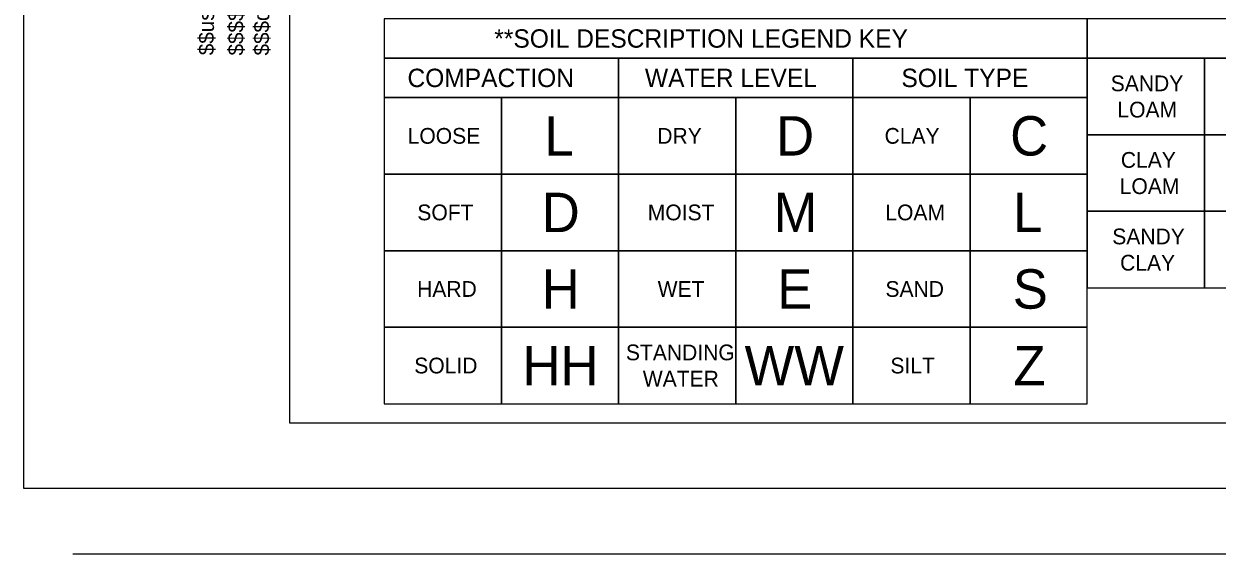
# Model space of a CAD drawing. Extents: x 14330 to 16126, y 15844 to 16994.
# Drawn here: x 14329.7 to 14784.3, y 15843.6 to 16045.6 of the extents above; entities that cross this region are included whole.
import ezdxf

# ---------------------------------------------------------------- set-up
doc = ezdxf.new("R2010")
doc.units = 0
for name, color, linetype in [('RD_SHT_Bndy', 7, 'Continuous'), ('RD_SHT_ID', 7, 'Continuous'), ('RD_SHT_Iplotshp', 7, 'Continuous'), ('RD_SHT_Snap', 7, 'Continuous'), ('RD_SHT_TX', 7, 'Continuous')]:
    doc.layers.add(name, color=color, linetype=linetype)

msp = doc.modelspace()

# ---------------------------------------------------------------- linework, layer by layer
at = {"layer": 'RD_SHT_Bndy'}
for p, q in [((14430.85, 16943.63), (14430.85, 15893.63)), ((14430.85, 16043.63), (14430.85, 15893.68)), ((14430.85, 15893.63), (16105.85, 15893.63)), ((16108.25, 15868.63), (14348.25, 15868.63)), ((16108.25, 15843.63), (14348.25, 15843.63))]:
    msp.add_line(p, q, dxfattribs=at)
for points in [[(14466.94, 16032.5), (14734.84, 16032.5), (14734.84, 16047.5), (14466.94, 16047.5)], [(14734.84, 16032.5), (15002.74, 16032.5), (15002.74, 16047.5), (14734.84, 16047.5)], [(14466.94, 16017.5), (14556.24, 16017.5), (14556.24, 16032.5), (14466.94, 16032.5)], [(14556.24, 16017.5), (14645.54, 16017.5), (14645.54, 16032.5), (14556.24, 16032.5)], [(14645.54, 16017.5), (14734.84, 16017.5), (14734.84, 16032.5), (14645.54, 16032.5)], [(14734.84, 16003.34), (14779.49, 16003.34), (14779.49, 16032.5), (14734.84, 16032.5)], [(14779.49, 16003.34), (14824.14, 16003.34), (14824.14, 16032.5), (14779.49, 16032.5)], [(14466.94, 15988.34), (14511.59, 15988.34), (14511.59, 16017.5), (14466.94, 16017.5)], [(14511.59, 15988.34), (14556.24, 15988.34), (14556.24, 16017.5), (14511.59, 16017.5)], [(14556.24, 15988.34), (14600.89, 15988.34), (14600.89, 16017.5), (14556.24, 16017.5)], [(14600.89, 15988.34), (14645.54, 15988.34), (14645.54, 16017.5), (14600.89, 16017.5)], [(14645.54, 15988.34), (14690.19, 15988.34), (14690.19, 16017.5), (14645.54, 16017.5)], [(14690.19, 15988.34), (14734.84, 15988.34), (14734.84, 16017.5), (14690.19, 16017.5)], [(14734.84, 15974.18), (14779.49, 15974.18), (14779.49, 16003.34), (14734.84, 16003.34)], [(14779.49, 15974.18), (14824.14, 15974.18), (14824.14, 16003.34), (14779.49, 16003.34)], [(14466.94, 15959.18), (14511.59, 15959.18), (14511.59, 15988.34), (14466.94, 15988.34)], [(14511.59, 15959.18), (14556.24, 15959.18), (14556.24, 15988.34), (14511.59, 15988.34)], [(14556.24, 15959.18), (14600.89, 15959.18), (14600.89, 15988.34), (14556.24, 15988.34)], [(14600.89, 15959.18), (14645.54, 15959.18), (14645.54, 15988.34), (14600.89, 15988.34)], [(14645.54, 15959.18), (14690.19, 15959.18), (14690.19, 15988.34), (14645.54, 15988.34)], [(14690.19, 15959.18), (14734.84, 15959.18), (14734.84, 15988.34), (14690.19, 15988.34)], [(14734.84, 15945.03), (14779.49, 15945.03), (14779.49, 15974.18), (14734.84, 15974.18)], [(14779.49, 15945.03), (14824.14, 15945.03), (14824.14, 15974.18), (14779.49, 15974.18)], [(14466.94, 15930.03), (14511.59, 15930.03), (14511.59, 15959.18), (14466.94, 15959.18)], [(14511.59, 15930.03), (14556.24, 15930.03), (14556.24, 15959.18), (14511.59, 15959.18)], [(14556.24, 15930.03), (14600.89, 15930.03), (14600.89, 15959.18), (14556.24, 15959.18)], [(14600.89, 15930.03), (14645.54, 15930.03), (14645.54, 15959.18), (14600.89, 15959.18)], [(14645.54, 15930.03), (14690.19, 15930.03), (14690.19, 15959.18), (14645.54, 15959.18)], [(14690.19, 15930.03), (14734.84, 15930.03), (14734.84, 15959.18), (14690.19, 15959.18)], [(14466.94, 15900.87), (14511.59, 15900.87), (14511.59, 15930.03), (14466.94, 15930.03)], [(14511.59, 15900.87), (14556.24, 15900.87), (14556.24, 15930.03), (14511.59, 15930.03)], [(14556.24, 15900.87), (14600.89, 15900.87), (14600.89, 15930.03), (14556.24, 15930.03)], [(14600.89, 15900.87), (14645.54, 15900.87), (14645.54, 15930.03), (14600.89, 15930.03)], [(14645.54, 15900.87), (14690.19, 15900.87), (14690.19, 15930.03), (14645.54, 15930.03)], [(14690.19, 15900.87), (14734.84, 15900.87), (14734.84, 15930.03), (14690.19, 15930.03)]]:
    msp.add_lwpolyline(points, close=True, dxfattribs=at)
at = {"layer": 'RD_SHT_Iplotshp'}
msp.add_lwpolyline([(14329.65, 16968.63), (16125.65, 16968.63), (16125.65, 15868.63), (14329.65, 15868.63)], close=True, dxfattribs=at)
at = {"layer": 'RD_SHT_Snap'}
msp.add_line((14329.65, 15868.63), (14329.65, 16968.63), dxfattribs=at)

# ---------------------------------------------------------------- texts
at = {"layer": 'RD_SHT_ID'}
for s, p in [('$$$$$$path$$$$$$$$filename$$$$$$$$', (14413.35, 16033.53)), ('$$$date$$$$', (14423.15, 16033.53)), ('$$user$$', (14402.1, 16033.63))]:
    msp.add_text(s, height=5.88, rotation=90, dxfattribs=at).set_placement(p)
at = {"layer": 'RD_SHT_TX'}
for s, p in [('**SOIL DESCRIPTION LEGEND KEY', (14508.89, 16036.5)), ('COMPACTION', (14475.81, 16021.5)), ('WATER LEVEL', (14566.29, 16021.5)), ('SOIL TYPE', (14664.01, 16021.5))]:
    msp.add_text(s, height=7, rotation=360, dxfattribs=at).set_placement(p)
for s, height, p in [('SANDY', 6, (14743.77, 16019.92)), ('LOAM', 6, (14746.32, 16009.92)), ('L', 15, (14527.97, 15995.42)), ('D', 15, (14616.28, 15995.42)), ('C', 15, (14705.44, 15995.42)), ('LOOSE', 6, (14475.89, 15999.92)), ('DRY', 6, (14571.01, 15999.92)), ('CLAY', 6, (14657.61, 15999.92)), ('CLAY', 6, (14747.62, 15990.76)), ('LOAM', 6, (14747.19, 15980.76)), ('SOFT', 6, (14479.58, 15970.76)), ('D', 15, (14526.98, 15966.26)), ('MOIST', 6, (14567.37, 15970.76)), ('M', 15, (14615.29, 15966.26)), ('LOAM', 6, (14657.89, 15970.76)), ('L', 15, (14706.57, 15966.26)), ('SANDY', 6, (14744.36, 15961.61)), ('CLAY', 6, (14747.34, 15951.61)), ('H', 15, (14526.98, 15937.11)), ('E', 15, (14616.71, 15937.11)), ('S', 15, (14706.43, 15937.11)), ('HARD', 6, (14479.49, 15941.61)), ('WET', 6, (14571.15, 15941.61)), ('SAND', 6, (14657.94, 15941.61)), ('HH', 15, (14519.63, 15907.95)), ('STANDING', 6, (14559.05, 15917.45)), ('WW', 15, (14604.26, 15907.95)), ('Z', 15, (14706.71, 15907.95)), ('SOLID', 6, (14478.4, 15912.45)), ('SILT', 6, (14659.83, 15912.45)), ('WATER', 6, (14565.48, 15907.45))]:
    msp.add_text(s, height=height, dxfattribs=at).set_placement(p)

doc.saveas('drawing.dxf')
